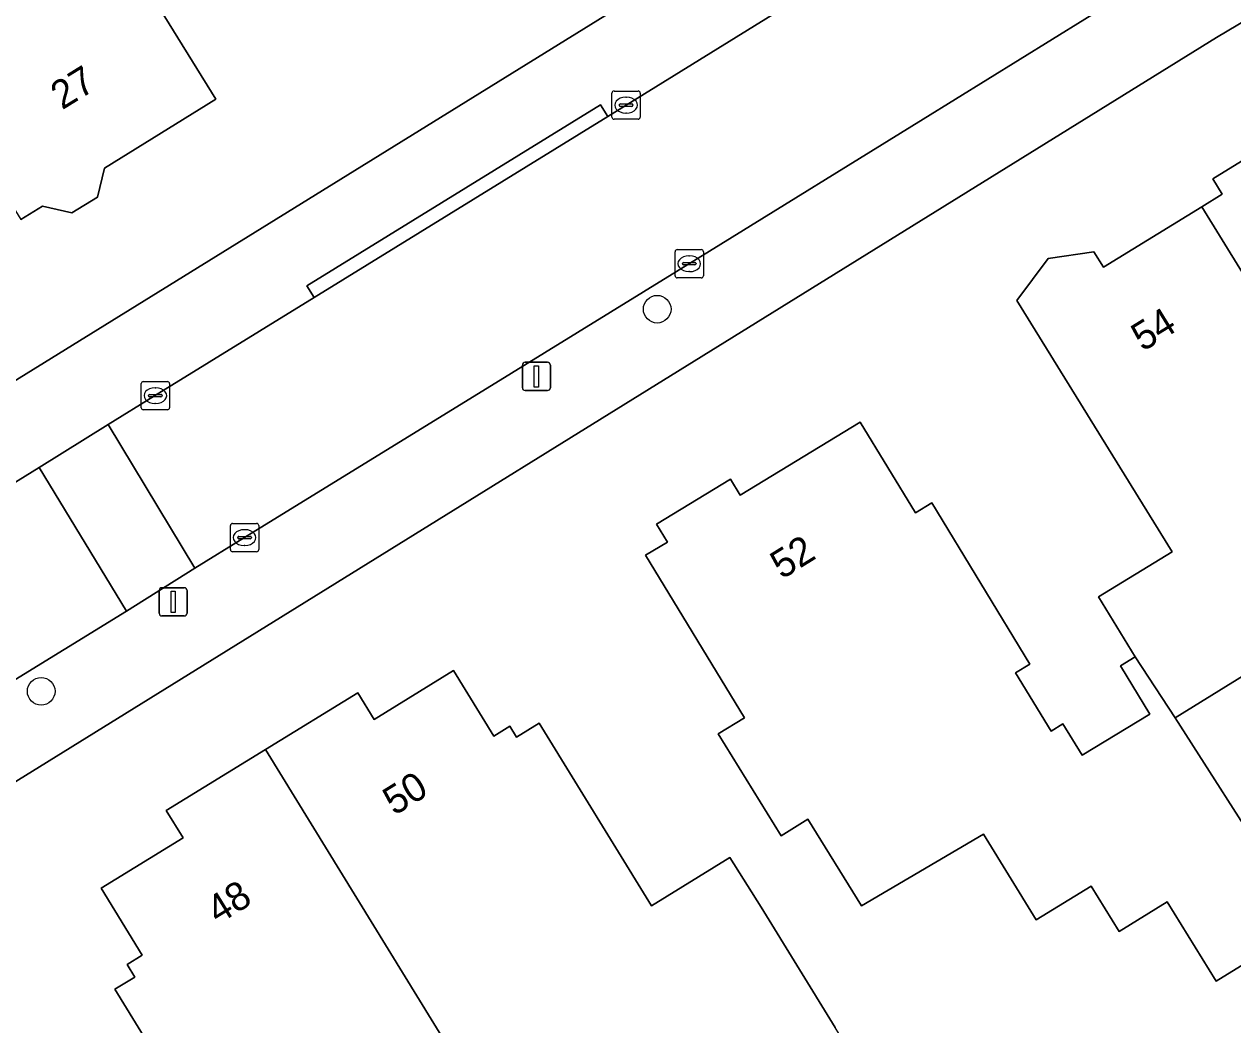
# Model space of a CAD drawing. Extents: x 161347 to 161881, y 382161 to 382804.
# Drawn here: x 161629.51 to 161672.27, y 382271.62 to 382307.02 of the extents above; entities that cross this region are included whole.
import ezdxf

# ---------------------------------------------------------------- set-up
doc = ezdxf.new("R2010")
doc.units = 0
for name, color, linetype in [('IMGEO_Boom', 7, 'Continuous'), ('IMGEO_Erf', 7, 'Continuous'), ('IMGEO_Kolk', 7, 'Continuous'), ('IMGEO_Lichtmast', 7, 'Continuous'), ('IMGEO_Pand', 7, 'Continuous'), ('IMGEO_Pand_nummerreeks', 7, 'Continuous'), ('IMGEO_Rijbaan_lokaal_open', 7, 'Continuous'), ('IMGEO_Voetpad_open', 7, 'Continuous')]:
    doc.layers.add(name, color=color, linetype=linetype)

msp = doc.modelspace()

# ---------------------------------------------------------------- linework, layer by layer
at = {"layer": 'IMGEO_Boom'}
for centre in [(161651.905, 382296.937), (161630.115, 382283.419)]:
    msp.add_circle(centre, 0.489, dxfattribs=at)
at = {"layer": 'IMGEO_Erf'}
for points in [[(161627.927, 382323.616), (161630.537, 382319.392), (161633.165, 382315.138), (161630.612, 382313.56), (161636.293, 382304.363), (161632.349, 382301.927), (161632.107, 382300.902), (161631.199, 382300.341), (161630.161, 382300.586), (161629.4, 382300.115)], [(161612.505, 382284.052), (161619.461, 382288.113), (161619.333, 382288.314), (161666.754, 382317.654)], [(161714.958, 382287.913), (161711.315, 382289.649), (161703.155, 382293.259), (161697.545, 382295.944), (161686.732, 382302.424), (161677.151, 382309.804), (161671.693, 382306.549), (161622.353, 382275.985)], [(161673.158, 382274.073), (161671.683, 382273.162), (161669.948, 382275.971), (161668.247, 382274.921), (161667.255, 382276.529), (161665.316, 382275.331), (161663.444, 382278.362), (161659.128, 382275.826), (161657.239, 382278.891), (161656.294, 382278.307), (161654.065, 382281.914), (161654.988, 382282.484), (161651.496, 382288.229), (161652.266, 382288.697), (161651.878, 382289.335), (161654.498, 382290.928), (161654.842, 382290.362), (161659.084, 382292.941), (161661.037, 382289.729), (161661.618, 382290.083), (161665.089, 382284.376), (161664.586, 382284.071), (161665.842, 382282.01), (161666.26, 382282.264), (161666.934, 382281.158), (161669.328, 382282.615), (161668.291, 382284.319), (161668.811, 382284.635), (161667.515, 382286.765), (161670.122, 382288.352), (161664.633, 382297.242), (161665.731, 382298.729), (161667.357, 382298.964), (161667.693, 382298.419), (161671.167, 382300.564), (161671.893, 382301.012), (161671.563, 382301.546), (161676.863, 382304.819)], [(161674.21, 382284.94), (161670.232, 382282.483), (161677.138, 382271.674)], [(161637.748, 382264.697), (161632.722, 382272.877), (161633.427, 382273.31), (161633.155, 382273.753), (161633.687, 382274.081), (161632.231, 382276.452), (161635.132, 382278.235), (161634.538, 382279.202), (161638.045, 382281.357), (161641.317, 382283.367), (161641.895, 382282.426), (161644.704, 382284.152), (161646.127, 382281.836), (161646.693, 382282.184), (161646.932, 382281.795), (161647.731, 382282.286), (161651.7, 382275.829), (161654.477, 382277.536), (161655.579, 382275.783), (161658.197, 382271.524)]]:
    msp.add_lwpolyline(points, dxfattribs=at)
at = {"layer": 'IMGEO_Kolk'}
for p, q in [((161650.306, 382303.73), (161650.306, 382304.582)), ((161650.381, 382304.656), (161651.233, 382304.656)), ((161651.307, 382304.582), (161651.307, 382303.73)), ((161650.565, 382304.15), (161650.565, 382304.162)), ((161651.003, 382304.113), (161650.605, 382304.113)), ((161650.608, 382304.199), (161651.006, 382304.199)), ((161650.794, 382304.436), (161650.819, 382304.436)), ((161651.049, 382304.162), (161651.049, 382304.15)), ((161651.233, 382303.656), (161650.381, 382303.656)), ((161650.817, 382303.876), (161650.792, 382303.876)), ((161652.539, 382298.12), (161652.539, 382298.972)), ((161652.614, 382299.046), (161653.466, 382299.046)), ((161653.54, 382298.972), (161653.54, 382298.12)), ((161652.798, 382298.54), (161652.798, 382298.552)), ((161653.236, 382298.503), (161652.838, 382298.503)), ((161652.841, 382298.589), (161653.239, 382298.589)), ((161653.027, 382298.826), (161653.052, 382298.826)), ((161653.282, 382298.552), (161653.282, 382298.54)), ((161653.05, 382298.266), (161653.025, 382298.266)), ((161653.466, 382298.046), (161652.614, 382298.046)), ((161633.653, 382293.452), (161633.653, 382294.304)), ((161633.728, 382294.378), (161634.58, 382294.378)), ((161634.654, 382294.304), (161634.654, 382293.452)), ((161633.912, 382293.872), (161633.912, 382293.884)), ((161634.35, 382293.835), (161633.952, 382293.835)), ((161633.955, 382293.921), (161634.353, 382293.921)), ((161634.141, 382294.158), (161634.166, 382294.158)), ((161634.396, 382293.884), (161634.396, 382293.872)), ((161634.58, 382293.378), (161633.728, 382293.378)), ((161634.164, 382293.598), (161634.139, 382293.598)), ((161636.808, 382288.431), (161636.808, 382289.283)), ((161636.883, 382289.357), (161637.735, 382289.357)), ((161637.296, 382289.137), (161637.321, 382289.137)), ((161637.809, 382289.283), (161637.809, 382288.431)), ((161637.067, 382288.851), (161637.067, 382288.863)), ((161637.505, 382288.814), (161637.107, 382288.814)), ((161637.11, 382288.9), (161637.508, 382288.9)), ((161637.551, 382288.863), (161637.551, 382288.851)), ((161637.735, 382288.357), (161636.883, 382288.357)), ((161637.319, 382288.577), (161637.294, 382288.577))]:
    msp.add_line(p, q, dxfattribs=at)
for points in [[(161650.306, 382303.73), (161650.306, 382304.582)], [(161650.381, 382304.656), (161651.233, 382304.656)], [(161651.307, 382304.582), (161651.307, 382303.73)], [(161651.233, 382303.656), (161650.381, 382303.656)], [(161652.539, 382298.12), (161652.539, 382298.972)], [(161652.614, 382299.046), (161653.466, 382299.046)], [(161653.54, 382298.972), (161653.54, 382298.12)], [(161653.466, 382298.046), (161652.614, 382298.046)], [(161633.653, 382293.452), (161633.653, 382294.304)], [(161633.728, 382294.378), (161634.58, 382294.378)], [(161634.654, 382294.304), (161634.654, 382293.452)], [(161634.58, 382293.378), (161633.728, 382293.378)], [(161636.808, 382288.431), (161636.808, 382289.283)], [(161636.883, 382289.357), (161637.735, 382289.357)], [(161637.809, 382289.283), (161637.809, 382288.431)], [(161637.735, 382288.357), (161636.883, 382288.357)]]:
    msp.add_lwpolyline(points, dxfattribs=at)
for centre, radius, start, end in [((161650.383, 382304.58), 0.0765, 91.552, 178.448), ((161650.383, 382304.58), 0.0765, 91.552, 178.448), ((161651.231, 382304.58), 0.0765, 1.552, 88.448), ((161651.231, 382304.58), 0.0765, 1.552, 88.448), ((161650.605, 382304.159), 0.0403, 85.8775, 175.7526), ((161650.602, 382304.149), 0.0366, 178.938, 274.7102), ((161651.006, 382304.156), 0.043, 264.8664, 352.4533), ((161651.01, 382304.161), 0.0386, 1.7309, 96.639), ((161650.383, 382303.732), 0.0765, 181.552, 268.448), ((161650.383, 382303.732), 0.0765, 181.552, 268.448), ((161651.231, 382303.732), 0.0765, 271.552, 358.448), ((161651.231, 382303.732), 0.0765, 271.552, 358.448), ((161652.616, 382298.97), 0.0765, 91.552, 178.448), ((161652.616, 382298.97), 0.0765, 91.552, 178.448), ((161653.464, 382298.97), 0.0765, 1.552, 88.448), ((161653.464, 382298.97), 0.0765, 1.552, 88.448), ((161652.838, 382298.549), 0.0403, 85.8775, 175.7526), ((161652.835, 382298.539), 0.0366, 178.938, 274.7102), ((161653.239, 382298.546), 0.043, 264.8664, 352.4533), ((161653.243, 382298.551), 0.0386, 1.7309, 96.639), ((161652.616, 382298.122), 0.0765, 181.552, 268.448), ((161652.616, 382298.122), 0.0765, 181.552, 268.448), ((161653.464, 382298.122), 0.0765, 271.552, 358.448), ((161653.464, 382298.122), 0.0765, 271.552, 358.448), ((161633.73, 382294.302), 0.0765, 91.552, 178.448), ((161633.73, 382294.302), 0.0765, 91.552, 178.448), ((161634.578, 382294.302), 0.0765, 1.552, 88.448), ((161634.578, 382294.302), 0.0765, 1.552, 88.448), ((161633.952, 382293.881), 0.0403, 85.8775, 175.7526), ((161633.949, 382293.871), 0.0366, 178.938, 274.7102), ((161634.353, 382293.878), 0.043, 264.8664, 352.4533), ((161634.357, 382293.883), 0.0386, 1.7309, 96.639), ((161633.73, 382293.454), 0.0765, 181.552, 268.448), ((161633.73, 382293.454), 0.0765, 181.552, 268.448), ((161634.578, 382293.454), 0.0765, 271.552, 358.448), ((161634.578, 382293.454), 0.0765, 271.552, 358.448), ((161636.885, 382289.281), 0.0765, 91.552, 178.448), ((161636.885, 382289.281), 0.0765, 91.552, 178.448), ((161637.733, 382289.281), 0.0765, 1.552, 88.448), ((161637.733, 382289.281), 0.0765, 1.552, 88.448), ((161637.107, 382288.86), 0.0403, 85.8775, 175.7526), ((161637.104, 382288.85), 0.0366, 178.938, 274.7102), ((161637.508, 382288.857), 0.043, 264.8664, 352.4533), ((161637.512, 382288.862), 0.0386, 1.7309, 96.639), ((161636.885, 382288.433), 0.0765, 181.552, 268.448), ((161636.885, 382288.433), 0.0765, 181.552, 268.448), ((161637.733, 382288.433), 0.0765, 271.552, 358.448), ((161637.733, 382288.433), 0.0765, 271.552, 358.448)]:
    msp.add_arc(centre, radius, start, end, dxfattribs=at)
for centre, major_axis, ratio, start_param, end_param in [((161650.793, 382304.156), (-0.387, 0.002), 0.722429, 4.712389, 7.853982), ((161650.818, 382304.156), (-0.39, 0.002), 0.717154, 1.570796, 4.712389), ((161653.026, 382298.546), (-0.387, 0.002), 0.722429, 4.712389, 7.853982), ((161653.051, 382298.546), (-0.39, 0.002), 0.717154, 1.570796, 4.712389), ((161634.14, 382293.878), (-0.387, 0.002), 0.722429, 4.712389, 7.853982), ((161634.165, 382293.878), (-0.39, 0.002), 0.717154, 1.570796, 4.712389), ((161637.295, 382288.857), (-0.387, 0.002), 0.722429, 4.712389, 7.853982), ((161637.32, 382288.857), (-0.39, 0.002), 0.717154, 1.570796, 4.712389)]:
    msp.add_ellipse(centre, major_axis=major_axis, ratio=ratio, start_param=start_param, end_param=end_param, dxfattribs=at)
at = {"layer": 'IMGEO_Lichtmast'}
for p, q in [((161647.137, 382294.159), (161647.137, 382294.959)), ((161647.137, 382294.959), (161647.137, 382294.159)), ((161647.237, 382295.059), (161648.027, 382295.059)), ((161648.027, 382295.059), (161647.237, 382295.059)), ((161648.127, 382294.959), (161648.127, 382294.159)), ((161648.127, 382294.159), (161648.127, 382294.959)), ((161648.027, 382294.059), (161647.237, 382294.059)), ((161647.237, 382294.059), (161648.027, 382294.059)), ((161634.288, 382286.183), (161634.288, 382286.983)), ((161634.288, 382286.983), (161634.288, 382286.183)), ((161634.388, 382287.083), (161635.178, 382287.083)), ((161635.178, 382287.083), (161634.388, 382287.083)), ((161635.278, 382286.983), (161635.278, 382286.183)), ((161635.278, 382286.183), (161635.278, 382286.983)), ((161635.178, 382286.083), (161634.388, 382286.083)), ((161634.388, 382286.083), (161635.178, 382286.083))]:
    msp.add_line(p, q, dxfattribs=at)
for points in [[(161647.557, 382294.934), (161647.707, 382294.934), (161647.707, 382294.184), (161647.557, 382294.184), (161647.557, 382294.934)], [(161634.708, 382286.958), (161634.858, 382286.958), (161634.858, 382286.208), (161634.708, 382286.208), (161634.708, 382286.958)]]:
    msp.add_lwpolyline(points, dxfattribs=at)
for centre, start, end in [((161647.237, 382294.959), 90, 180), ((161647.237, 382294.959), 90, 180), ((161648.027, 382294.959), 0, 90), ((161648.027, 382294.959), 360, 90), ((161647.237, 382294.159), 180, 270), ((161647.237, 382294.159), 180, 270), ((161648.027, 382294.159), 270, 0), ((161648.027, 382294.159), 270, 0), ((161634.388, 382286.983), 90, 180), ((161634.388, 382286.983), 90, 180), ((161635.178, 382286.983), 0, 90), ((161635.178, 382286.983), 360, 90), ((161634.388, 382286.183), 180, 270), ((161634.388, 382286.183), 180, 270), ((161635.178, 382286.183), 270, 0), ((161635.178, 382286.183), 270, 0)]:
    msp.add_arc(centre, 0.1, start, end, dxfattribs=at)
at = {"layer": 'IMGEO_Pand'}
for points in [[(161629.4, 382300.115), (161630.161, 382300.586), (161631.199, 382300.341), (161632.107, 382300.902), (161632.349, 382301.927), (161636.293, 382304.363), (161630.612, 382313.56), (161633.165, 382315.138), (161630.537, 382319.392), (161627.927, 382323.616), (161624.985, 382321.799), (161628.545, 382316.037), (161622.141, 382312.082), (161622.812, 382310.996), (161622.718, 382310.938)], [(161676.982, 382289.356), (161679.576, 382290.958), (161677.589, 382294.173), (161683.024, 382297.53), (161683.372, 382299.001), (161682.252, 382300.815), (161680.7, 382301.182), (161679.556, 382300.475), (161678.52, 382302.152), (161678.466, 382303.955), (161676.863, 382304.819), (161671.563, 382301.546), (161671.893, 382301.012), (161671.167, 382300.564), (161676.401, 382292.075), (161675.569, 382291.551)], [(161668.811, 382284.635), (161670.232, 382282.483), (161674.21, 382284.94), (161678.191, 382287.399), (161676.982, 382289.356), (161675.569, 382291.551), (161676.401, 382292.075), (161671.167, 382300.564), (161667.693, 382298.419), (161667.357, 382298.964), (161665.731, 382298.729), (161664.633, 382297.242), (161670.122, 382288.352), (161667.515, 382286.765)], [(161649.162, 382271.205), (161651.508, 382267.386), (161654.12, 382269.001), (161656.377, 382265.35), (161660.453, 382267.871), (161658.721, 382270.672), (161658.197, 382271.524), (161655.579, 382275.783), (161654.477, 382277.536), (161651.7, 382275.829), (161647.731, 382282.286), (161646.932, 382281.795), (161646.693, 382282.184), (161646.127, 382281.836), (161644.704, 382284.152), (161641.895, 382282.426), (161641.317, 382283.367), (161638.045, 382281.357), (161645.623, 382269.03)], [(161645.623, 382269.03), (161638.045, 382281.357), (161634.538, 382279.202), (161635.132, 382278.235), (161632.231, 382276.452), (161633.687, 382274.081), (161633.155, 382273.753), (161633.427, 382273.31), (161632.722, 382272.877), (161637.748, 382264.697), (161634.981, 382262.997), (161636.457, 382260.596), (161639.362, 382256.214), (161640.853, 382253.965), (161641.033, 382253.694), (161643.843, 382255.393), (161641.053, 382259.934), (161639.781, 382262.004), (161639.874, 382262.061), (161640.191, 382262.256), (161643.529, 382264.307), (161641.996, 382266.802)]]:
    msp.add_lwpolyline(points, close=True, dxfattribs=at)
msp.add_lwpolyline([(161677.138, 382271.674), (161670.232, 382282.483), (161668.811, 382284.635), (161668.291, 382284.319), (161669.328, 382282.615), (161666.934, 382281.158), (161666.26, 382282.264), (161665.842, 382282.01), (161664.586, 382284.071), (161665.089, 382284.376), (161661.618, 382290.083), (161661.037, 382289.729), (161659.084, 382292.941), (161654.842, 382290.362), (161654.498, 382290.928), (161651.878, 382289.335), (161652.266, 382288.697), (161651.496, 382288.229), (161654.988, 382282.484), (161654.065, 382281.914), (161656.294, 382278.307), (161657.239, 382278.891), (161659.128, 382275.826), (161663.444, 382278.362), (161665.316, 382275.331), (161667.255, 382276.529), (161668.247, 382274.921), (161669.948, 382275.971), (161671.683, 382273.162), (161673.158, 382274.073)], dxfattribs=at)
at = {"layer": 'IMGEO_Rijbaan_lokaal_open'}
for points in [[(161668.184, 382314.902), (161666.523, 382313.889), (161650.804, 382304.153), (161650.157, 382303.754), (161639.777, 382297.347), (161634.126, 382293.868), (161632.48, 382292.857), (161635.555, 382287.777), (161637.303, 382288.856), (161641.382, 382291.368), (161645.583, 382293.956), (161653.759, 382298.992), (161661.309, 382303.664), (161675.035, 382312.158)], [(161618.896, 382277.584), (161620.383, 382278.485), (161628.112, 382283.168), (161628.72, 382283.536), (161633.128, 382286.258), (161630.045, 382291.331), (161627.466, 382289.739), (161620.698, 382285.57)]]:
    msp.add_lwpolyline(points, dxfattribs=at)
msp.add_lwpolyline([(161633.128, 382286.258), (161635.555, 382287.777), (161632.48, 382292.857), (161630.045, 382291.331)], close=True, dxfattribs=at)
at = {"layer": 'IMGEO_Voetpad_open'}
for points in [[(161620.698, 382285.57), (161627.466, 382289.739), (161630.045, 382291.331), (161632.48, 382292.857), (161634.126, 382293.868), (161639.777, 382297.347), (161639.517, 382297.769), (161649.9, 382304.17), (161650.157, 382303.754), (161650.804, 382304.153), (161666.523, 382313.889), (161668.184, 382314.902), (161666.754, 382317.654), (161619.333, 382288.314), (161619.461, 382288.113), (161612.505, 382284.052)], [(161671.693, 382306.549), (161677.151, 382309.804), (161675.035, 382312.158), (161661.309, 382303.664), (161653.759, 382298.992), (161645.583, 382293.956), (161641.382, 382291.368), (161637.303, 382288.856), (161635.555, 382287.777), (161633.128, 382286.258), (161628.72, 382283.536), (161628.112, 382283.168), (161620.383, 382278.485), (161618.896, 382277.584)], [(161622.353, 382275.985), (161671.693, 382306.549)]]:
    msp.add_lwpolyline(points, dxfattribs=at)
msp.add_lwpolyline([(161650.157, 382303.754), (161649.9, 382304.17), (161639.517, 382297.769), (161639.777, 382297.347)], close=True, dxfattribs=at)

# ---------------------------------------------------------------- texts
at = {"layer": 'IMGEO_Pand_nummerreeks'}
for s, rotation, p in [('27', 31.6496, (161630.856, 382303.972)), ('54', 31.6904, (161669.08, 382295.419)), ('52', 31.8395, (161656.316, 382287.361)), ('50', 31.6884, (161642.608, 382279.003)), ('48', 31.6903, (161636.372, 382275.154))]:
    msp.add_text(s, height=1, rotation=rotation, dxfattribs=at).set_placement(p)

doc.saveas('drawing.dxf')
